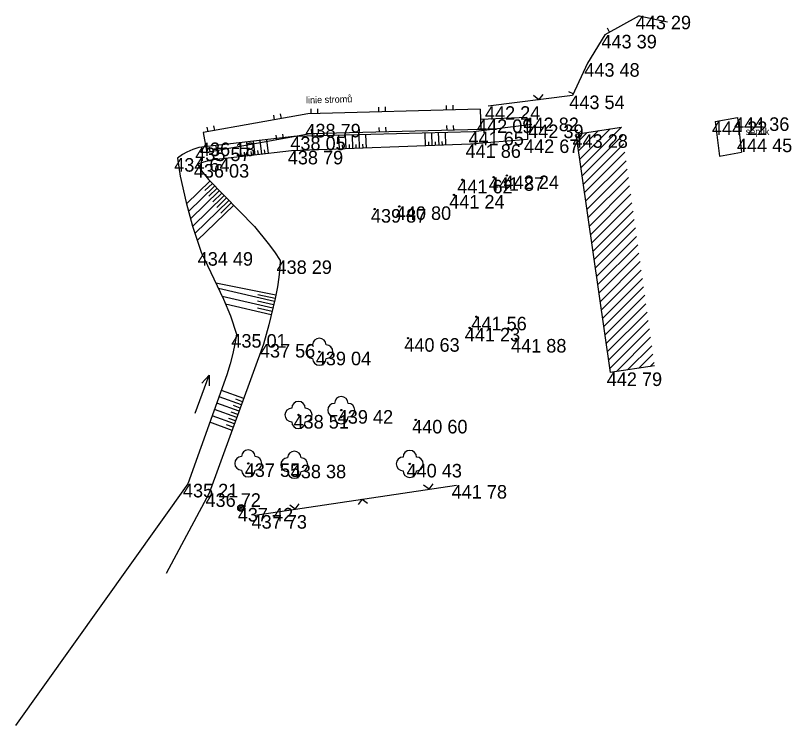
# Model space of a CAD drawing. Extents: x -554123 to -553118, y -1076825 to -1073672.
# Drawn here: x -553909.8 to -553852.4, y -1074233.4 to -1074181 of the extents above; entities that cross this region are included whole.
import ezdxf

# ---------------------------------------------------------------- set-up
doc = ezdxf.new("R2010")
doc.units = 0
for name, color, linetype in [('1', 7, 'Continuous'), ('12', 7, 'Continuous'), ('14', 7, 'Continuous'), ('18', 7, 'Continuous'), ('20', 7, 'Continuous'), ('26', 7, 'Continuous'), ('27', 7, 'Continuous'), ('28', 7, 'Continuous'), ('32', 7, 'Continuous'), ('34', 7, 'Continuous'), ('52', 7, 'Continuous'), ('6', 7, 'Continuous')]:
    doc.layers.add(name, color=color, linetype=linetype)

# ---------------------------------------------------------------- blocks, each defined once
blk = doc.blocks.new('POINT_DISPLAY')
blk.add_line((0, 0), (0, 0))
blk = doc.blocks.new('SLDP')
at = {"layer": '20'}
for radius in [0.25, 0.158, 0.05]:
    blk.add_circle((0, 0), radius, dxfattribs=at)
blk = doc.blocks.new('T')
at = {"layer": '6'}
blk.add_circle((0, 0), 0.05, dxfattribs=at)
blk = doc.blocks.new('STL')
at = {"layer": '34'}
blk.add_circle((0, 0), 0.05, dxfattribs=at)
for centre, start, end in [((0, 0.5), 0, 180), ((-0.5, 0), 90, 270), ((0.5, 0), 270, 90), ((0, -0.5), 180, 0)]:
    blk.add_arc(centre, 0.5, start, end, dxfattribs=at)
blk = doc.blocks.new('VOTOK')
at = {"layer": '28'}
for p, q in [((-3.001, 0), (0, 0)), ((-0.75, 0.282), (0, 0)), ((0, 0), (-0.75, -0.28))]:
    blk.add_line(p, q, dxfattribs=at)

msp = doc.modelspace()

# ---------------------------------------------------------------- linework, layer by layer
at = {"layer": '12'}
for p, q in [((-553863.68, -1074181.01), (-553866.21, -1074182.42)), ((-553863.68, -1074181.01), (-553861.58, -1074181.45)), ((-553865.864, -1074182.227), (-553866.034, -1074181.921)), ((-553866.21, -1074182.42), (-553867.5, -1074184.51)), ((-553867.5, -1074184.51), (-553868.61, -1074186.9)), ((-553868.553, -1074186.777), (-553868.87, -1074186.63)), ((-553868.61, -1074186.9), (-553874.84, -1074187.69)), ((-553871.09, -1074187.214), (-553871.486, -1074186.908)), ((-553871.09, -1074187.214), (-553870.783, -1074186.819)), ((-553875.419, -1074187.91), (-553888.15, -1074188.242)), ((-553887.915, -1074188.236), (-553887.924, -1074187.886)), ((-553887.415, -1074188.223), (-553887.424, -1074187.873)), ((-553882.916, -1074188.106), (-553882.926, -1074187.756)), ((-553882.417, -1074188.092), (-553882.426, -1074187.743)), ((-553877.918, -1074187.975), (-553877.927, -1074187.625)), ((-553877.418, -1074187.962), (-553877.427, -1074187.612)), ((-553875.419, -1074187.91), (-553875.38, -1074189.409)), ((-553888.15, -1074188.242), (-553895.882, -1074189.631)), ((-553890.611, -1074188.684), (-553890.672, -1074188.34)), ((-553890.118, -1074188.596), (-553890.18, -1074188.251)), ((-553895.882, -1074189.631), (-553895.617, -1074191.108)), ((-553895.532, -1074189.568), (-553895.594, -1074189.224)), ((-553895.04, -1074189.48), (-553895.102, -1074189.135)), ((-553875.38, -1074189.409), (-553887.989, -1074189.737)), ((-553887.876, -1074189.734), (-553887.885, -1074189.384)), ((-553887.376, -1074189.721), (-553887.385, -1074189.371)), ((-553882.877, -1074189.604), (-553882.887, -1074189.254)), ((-553882.378, -1074189.591), (-553882.387, -1074189.241)), ((-553877.879, -1074189.474), (-553877.888, -1074189.124)), ((-553877.379, -1074189.461), (-553877.388, -1074189.111)), ((-553887.989, -1074189.737), (-553895.617, -1074191.108)), ((-553890.45, -1074190.179), (-553890.511, -1074189.835)), ((-553889.957, -1074190.091), (-553890.019, -1074189.746)), ((-553895.371, -1074191.064), (-553895.433, -1074190.719)), ((-553894.879, -1074190.975), (-553894.941, -1074190.631)), ((-553892.06, -1074217.87), (-553877.18, -1074215.65)), ((-553879.202, -1074215.952), (-553879.605, -1074215.654)), ((-553879.202, -1074215.952), (-553878.904, -1074215.549)), ((-553889.093, -1074217.427), (-553889.495, -1074217.129)), ((-553889.093, -1074217.427), (-553888.795, -1074217.025)), ((-553884.148, -1074216.69), (-553884.445, -1074217.092)), ((-553884.148, -1074216.69), (-553883.745, -1074216.987))]:
    msp.add_line(p, q, dxfattribs=at)
at = {"layer": '14'}
for p, q in [((-553868.36, -1074189.76), (-553864.997, -1074189.225)), ((-553868.36, -1074189.76), (-553865.82, -1074207.34)), ((-553862.548, -1074206.851), (-553865.82, -1074207.34))]:
    msp.add_line(p, q, dxfattribs=at)
at = {"layer": '18'}
for p, q in [((-553858.07, -1074188.81), (-553856.43, -1074188.51)), ((-553856.43, -1074188.51), (-553856.12, -1074191.072)), ((-553858.07, -1074188.81), (-553857.76, -1074191.372)), ((-553857.76, -1074191.372), (-553856.12, -1074191.072))]:
    msp.add_line(p, q, dxfattribs=at)
at = {"layer": '26'}
for p, q in [((-553879.468, -1074190.621), (-553879.503, -1074189.667)), ((-553878.968, -1074190.603), (-553879.002, -1074189.654)), ((-553878.469, -1074190.584), (-553878.503, -1074189.64)), ((-553877.969, -1074190.566), (-553878.003, -1074189.627)), ((-553891.565, -1074191.239), (-553891.685, -1074190.217)), ((-553891.069, -1074191.18), (-553891.189, -1074190.16)), ((-553885.832, -1074190.852), (-553885.869, -1074189.84)), ((-553885.332, -1074190.834), (-553885.369, -1074189.826)), ((-553884.833, -1074190.815), (-553884.869, -1074189.813)), ((-553884.333, -1074190.797), (-553884.369, -1074189.799)), ((-553883.833, -1074190.779), (-553883.869, -1074189.786)), ((-553893.055, -1074191.414), (-553893.176, -1074190.389)), ((-553892.558, -1074191.356), (-553892.679, -1074190.332)), ((-553892.062, -1074191.297), (-553892.182, -1074190.275)), ((-553885.582, -1074190.843), (-553885.593, -1074190.54)), ((-553885.083, -1074190.824), (-553885.093, -1074190.523)), ((-553884.583, -1074190.806), (-553884.594, -1074190.506)), ((-553884.083, -1074190.788), (-553884.094, -1074190.489)), ((-553879.218, -1074190.612), (-553879.229, -1074190.326)), ((-553878.719, -1074190.594), (-553878.729, -1074190.31)), ((-553878.219, -1074190.575), (-553878.229, -1074190.293)), ((-553892.807, -1074191.385), (-553892.843, -1074191.078)), ((-553892.31, -1074191.327), (-553892.346, -1074191.019)), ((-553891.814, -1074191.268), (-553891.85, -1074190.961)), ((-553891.317, -1074191.21), (-553891.353, -1074190.903)), ((-553895.378, -1074193.201), (-553897.131, -1074194.899)), ((-553895.03, -1074193.56), (-553896.983, -1074195.452)), ((-553895.204, -1074193.381), (-553895.76, -1074193.919)), ((-553894.683, -1074193.92), (-553896.835, -1074196.004)), ((-553894.857, -1074193.74), (-553895.472, -1074194.336)), ((-553894.509, -1074194.099), (-553895.184, -1074194.753)), ((-553894.335, -1074194.279), (-553896.687, -1074196.557)), ((-553893.987, -1074194.638), (-553896.511, -1074197.082)), ((-553894.161, -1074194.458), (-553894.892, -1074195.167)), ((-553893.813, -1074194.818), (-553894.596, -1074195.576)), ((-553893.639, -1074194.997), (-553896.335, -1074197.608)), ((-553890.529, -1074201.625), (-553894.954, -1074200.747)), ((-553890.634, -1074202.114), (-553894.759, -1074201.154)), ((-553890.578, -1074201.87), (-553891.85, -1074201.618)), ((-553890.748, -1074202.601), (-553894.482, -1074201.732)), ((-553890.691, -1074202.358), (-553891.87, -1074202.083)), ((-553890.861, -1074203.088), (-553894.232, -1074202.303)), ((-553890.804, -1074202.845), (-553891.868, -1074202.597)), ((-553893.07, -1074209.735), (-553894.714, -1074209.136)), ((-553892.898, -1074209.265), (-553894.544, -1074208.664)), ((-553893.241, -1074210.205), (-553894.882, -1074209.606)), ((-553892.984, -1074209.5), (-553893.478, -1074209.32)), ((-553893.412, -1074210.674), (-553895.051, -1074210.076)), ((-553893.327, -1074210.44), (-553893.819, -1074210.26)), ((-553893.155, -1074209.97), (-553893.648, -1074209.79)), ((-553893.584, -1074211.144), (-553895.22, -1074210.547)), ((-553893.498, -1074210.909), (-553893.989, -1074210.73)), ((-553893.755, -1074211.614), (-553895.389, -1074211.018)), ((-553893.669, -1074211.379), (-553894.16, -1074211.2))]:
    msp.add_line(p, q, dxfattribs=at)
at = {"layer": '27'}
for p, q in [((-553871.62, -1074189.04), (-553875.92, -1074189.57)), ((-553871.98, -1074188.53), (-553875.4, -1074188.66)), ((-553871.98, -1074188.53), (-553871.93, -1074190.14)), ((-553875.92, -1074189.57), (-553889.19, -1074189.93)), ((-553889.19, -1074189.93), (-553896.22, -1074190.74)), ((-553871.93, -1074190.14), (-553876.14, -1074190.5)), ((-553876.14, -1074190.5), (-553889.37, -1074190.98)), ((-553891.43, -1074205.24), (-553895.45, -1074216.26)), ((-553895.45, -1074216.26), (-553898.62, -1074222.19))]:
    msp.add_line(p, q, dxfattribs=at)
for points in [[(-553896.22, -1074190.74), (-553896.65, -1074190.879), (-553897.091, -1074191.083), (-553897.414, -1074191.261), (-553897.78, -1074191.52)], [(-553889.37, -1074190.98), (-553895.317, -1074191.681), (-553895.875, -1074191.81), (-553896.31, -1074191.96)], [(-553896.31, -1074191.96), (-553896.011, -1074192.452), (-553895.489, -1074193.087), (-553892.11, -1074196.576), (-553891.08, -1074197.822), (-553890.624, -1074198.439), (-553890.2, -1074199.07)], [(-553890.2, -1074199.07), (-553890.225, -1074199.593), (-553890.303, -1074200.302), (-553890.41, -1074201.024), (-553890.58, -1074201.881), (-553891.031, -1074203.818), (-553891.43, -1074205.24)]]:
    msp.add_lwpolyline(points, dxfattribs=at)
at = {"layer": '28'}
msp.add_line((-553897.02, -1074215.56), (-553909.755, -1074233.396), dxfattribs=at)
for points in [[(-553897.78, -1074191.52), (-553897.584, -1074192.859), (-553897.159, -1074194.795), (-553896.69, -1074196.547), (-553896.05, -1074198.46)], [(-553896.05, -1074198.46), (-553894.383, -1074201.938), (-553893.877, -1074203.159), (-553893.44, -1074204.51)], [(-553893.44, -1074204.51), (-553893.556, -1074205.22), (-553893.704, -1074205.935), (-553893.889, -1074206.713), (-553894.136, -1074207.527), (-553897.02, -1074215.56)]]:
    msp.add_lwpolyline(points, dxfattribs=at)
at = {"layer": '32'}
for p, q in [((-553868.271, -1074190.377), (-553867.52, -1074189.626)), ((-553868.182, -1074190.995), (-553866.679, -1074189.493)), ((-553868.092, -1074191.613), (-553865.838, -1074189.359)), ((-553868.003, -1074192.231), (-553864.997, -1074189.225)), ((-553867.914, -1074192.849), (-553864.911, -1074189.846)), ((-553867.824, -1074193.467), (-553864.824, -1074190.467)), ((-553867.735, -1074194.085), (-553864.738, -1074191.088)), ((-553867.646, -1074194.702), (-553864.652, -1074191.708)), ((-553867.557, -1074195.32), (-553864.566, -1074192.329)), ((-553867.467, -1074195.938), (-553864.479, -1074192.95)), ((-553867.378, -1074196.556), (-553864.393, -1074193.571)), ((-553867.289, -1074197.174), (-553864.307, -1074194.192)), ((-553867.2, -1074197.792), (-553864.221, -1074194.813)), ((-553867.11, -1074198.409), (-553864.134, -1074195.433)), ((-553867.021, -1074199.027), (-553864.048, -1074196.054)), ((-553866.932, -1074199.645), (-553863.962, -1074196.675)), ((-553866.843, -1074200.263), (-553863.876, -1074197.296)), ((-553866.753, -1074200.881), (-553863.789, -1074197.917)), ((-553866.664, -1074201.499), (-553863.703, -1074198.538)), ((-553866.575, -1074202.116), (-553863.617, -1074199.159)), ((-553866.485, -1074202.734), (-553863.531, -1074199.779)), ((-553866.396, -1074203.352), (-553863.444, -1074200.4)), ((-553866.307, -1074203.97), (-553863.358, -1074201.021)), ((-553866.218, -1074204.588), (-553863.272, -1074201.642)), ((-553866.128, -1074205.206), (-553863.186, -1074202.263)), ((-553866.039, -1074205.823), (-553863.099, -1074202.884)), ((-553865.95, -1074206.441), (-553863.013, -1074203.504)), ((-553865.861, -1074207.059), (-553862.927, -1074204.125)), ((-553865.367, -1074207.272), (-553862.84, -1074204.746)), ((-553864.535, -1074207.148), (-553862.754, -1074205.367)), ((-553863.704, -1074207.024), (-553862.668, -1074205.988)), ((-553862.873, -1074206.899), (-553862.582, -1074206.609))]:
    msp.add_line(p, q, dxfattribs=at)

# ---------------------------------------------------------------- block references
at = {"layer": '1'}
for p in [(-553863.68, -1074181.01), (-553866.21, -1074182.42), (-553867.5, -1074184.51), (-553868.61, -1074186.9), (-553874.84, -1074187.69), (-553856.43, -1074188.51), (-553888.07, -1074188.99), (-553875.4, -1074188.66), (-553871.98, -1074188.53), (-553871.62, -1074189.04), (-553858.07, -1074188.81), (-553875.92, -1074189.57), (-553889.19, -1074189.93), (-553871.93, -1074190.14), (-553868.36, -1074189.76), (-553856.24, -1074190.08), (-553896.22, -1074190.74), (-553895.75, -1074190.37), (-553876.14, -1074190.5), (-553889.37, -1074190.98), (-553897.78, -1074191.52), (-553896.31, -1074191.96), (-553874.44, -1074192.93), (-553873.46, -1074192.81), (-553876.75, -1074193.12), (-553877.37, -1074194.24), (-553883.23, -1074195.28), (-553881.41, -1074195.08), (-553896.05, -1074198.46), (-553890.2, -1074199.07), (-553875.71, -1074203.23), (-553893.44, -1074204.51), (-553876.21, -1074204.05), (-553880.77, -1074204.81), (-553872.79, -1074204.87), (-553891.43, -1074205.24), (-553887.31, -1074205.81), (-553865.82, -1074207.34), (-553885.69, -1074210.12), (-553888.85, -1074210.48), (-553880.19, -1074210.84), (-553892.56, -1074214.05), (-553889.16, -1074214.15), (-553880.63, -1074214.09), (-553897.02, -1074215.56), (-553877.18, -1074215.65), (-553895.45, -1074216.26), (-553893.09, -1074217.34), (-553892.06, -1074217.87)]:
    msp.add_blockref('POINT_DISPLAY', p, dxfattribs=at)
at = {"layer": '20'}
msp.add_blockref('SLDP', (-553893.09, -1074217.34), dxfattribs=at)
at = {"layer": '28', "xscale": 1.000000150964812, "yscale": 1.000000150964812, "rotation": 69.89950088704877}
msp.add_blockref('VOTOK', (-553895.457, -1074207.533), dxfattribs=at)
at = {"layer": '32'}
msp.add_blockref('POINT_DISPLAY', (-553864.997, -1074189.225), dxfattribs=at)
at = {"layer": '34'}
for p in [(-553887.31, -1074205.81), (-553885.69, -1074210.12), (-553888.85, -1074210.48), (-553892.56, -1074214.05), (-553889.16, -1074214.15), (-553880.63, -1074214.09)]:
    msp.add_blockref('STL', p, dxfattribs=at)
at = {"layer": '6'}
for p in [(-553876.75, -1074193.12), (-553874.44, -1074192.93), (-553873.46, -1074192.81), (-553877.37, -1074194.24), (-553883.23, -1074195.28), (-553881.41, -1074195.08), (-553875.71, -1074203.23), (-553876.21, -1074204.05), (-553880.77, -1074204.81), (-553872.79, -1074204.87), (-553880.19, -1074210.84)]:
    msp.add_blockref('T', p, dxfattribs=at)

# ---------------------------------------------------------------- texts
at = {"layer": '52'}
msp.add_text('linie stromů', height=0.5, rotation=1.49383, dxfattribs=at).set_placement((-553888.289, -1074187.485))
msp.add_text('septik', height=0.5, dxfattribs=at).set_placement((-553855.816, -1074189.808))
at = {"layer": '6'}
for s, p in [('443 29 ', (-553863.942, -1074182.01)), ('443 39 ', (-553866.472, -1074183.42)), ('443 48 ', (-553867.738, -1074185.51)), ('443 54 ', (-553868.848, -1074187.9)), ('442 24 ', (-553875.078, -1074188.69)), ('442 82 ', (-553872.23, -1074189.53)), ('444 36 ', (-553856.68, -1074189.51)), ('438 79 ', (-553888.342, -1074189.99)), ('442 09 ', (-553875.664, -1074189.66)), ('442 39 ', (-553871.882, -1074190.04)), ('444 22 ', (-553858.308, -1074189.81)), ('441 65 ', (-553876.291, -1074190.57)), ('438 05 ', (-553889.454, -1074190.93)), ('442 67 ', (-553872.19, -1074191.14)), ('443 28 ', (-553868.61, -1074190.76)), ('444 45 ', (-553856.466, -1074191.08)), ('435 57 ', (-553896.48, -1074191.74)), ('436 13 ', (-553896.133, -1074191.37)), ('441 86 ', (-553876.511, -1074191.5)), ('438 79 ', (-553889.642, -1074191.98)), ('434 64 ', (-553898.03, -1074192.52)), ('436 03 ', (-553896.586, -1074192.96)), ('441 62 ', (-553877.121, -1074194.12)), ('441 87 ', (-553874.797, -1074193.93)), ('442 24 ', (-553873.698, -1074193.81)), ('441 24 ', (-553877.717, -1074195.24)), ('439 87 ', (-553883.502, -1074196.28)), ('440 80 ', (-553881.664, -1074196.08)), ('434 49 ', (-553896.3, -1074199.46)), ('438 29 ', (-553890.474, -1074200.07)), ('441 56 ', (-553876.081, -1074204.23)), ('435 01 ', (-553893.811, -1074205.51)), ('441 23 ', (-553876.569, -1074205.05)), ('440 63 ', (-553881.034, -1074205.81)), ('441 88 ', (-553873.149, -1074205.87)), ('437 56 ', (-553891.702, -1074206.24)), ('439 04 ', (-553887.574, -1074206.81)), ('442 79 ', (-553866.08, -1074208.34)), ('439 42 ', (-553885.952, -1074211.12)), ('438 51 ', (-553889.219, -1074211.48)), ('440 60 ', (-553880.456, -1074211.84)), ('437 55 ', (-553892.82, -1074215.05)), ('438 38 ', (-553889.422, -1074215.15)), ('440 43 ', (-553880.87, -1074215.09)), ('435 21 ', (-553897.389, -1074216.56)), ('441 78 ', (-553877.537, -1074216.65)), ('436 72 ', (-553895.722, -1074217.26)), ('437 42 ', (-553893.338, -1074218.34)), ('437 73 ', (-553892.318, -1074218.87))]:
    msp.add_text(s, height=1, dxfattribs=at).set_placement(p)

doc.saveas('drawing.dxf')
